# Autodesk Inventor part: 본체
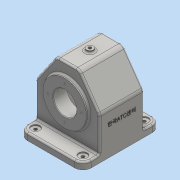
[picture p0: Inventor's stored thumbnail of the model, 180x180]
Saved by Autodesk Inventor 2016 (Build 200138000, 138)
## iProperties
Created: 2022-12
Part Number: 본체
Material: 일반
Document SubType Name: Modeling
Designer: PC-1-2
Density: 1 g/cm^3
Appearance: 기본값
Author: PC-1-2
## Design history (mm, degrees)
sketch "스케치1"
  geometry: L1 (-55, -67)-(55, -67); L2 (55, -67)-(55, 67); L3 (55, 67)-(-55, 67); L4 (-55, 67)-(-55, -67); L5 (-55, -67)-(55, 67); L6 (55, -67)-(-55, 67); 1 further point
  constraints: 12 end point, 2 midpoint, 2 parallel, 1 horizontal, 1 perpendicular
  dimensions: "d0" = 134 distance between parallel lines of L1 L3; "d1" = 110 distance between parallel lines of L2 L4
extrude "돌출1" new body sketch "스케치1" distance "d2" = 12; taper "d3" = 0 deg
sketch "스케치2"
  geometry: L1 (55, 12)-(-55, 12) reference; L2 (55, 12)-(55, 72); L3 (55, 72)-(19.99, 122); L4 (19.99, 122)-(-19.99, 122); L5 (-19.99, 122)-(-55, 72); L6 (-55, 72)-(-55, 12); L7 (55, 0)-(-55, 0) reference; 1 further point
  constraints: 10 end point, 1 horizontal alignment, 1 parallel, 1 perpendicular, 1 vertical
  dimensions: "d4" = 122 distance between parallel lines of L7 L4; "d5" = 72 distance from line of L7 L2.end; "d6" = 35 deg angle of L3 L2; "d7" = 35 deg angle of L6 L5
extrude "돌출2" join sketch "스케치2" stored distance "d8" = 77; taper "d9" = 0 deg
sketch "스케치3"
  geometry: C1 r 6 at (19.99, -38.5); 1 further point
  constraints: 1 centre point, 1 coincident
  dimensions: "d10" = 12 diameter of C1
extrude "돌출3" join sketch "스케치3" distance "d11" = 4; taper "d12" = 0 deg
sketch "스케치4"
  geometry: L1 (-55, 0)-(55, 0) reference; C1 r 37.5 at (0, 65); 2 further points
  constraints: 1 centre point, 1 midpoint, 1 vertical alignment
  dimensions: "d13" = 75 diameter of C1; "d14" = 65 distance from line of L1 C1.centre
extrude "돌출4" join sketch "스케치4" distance "d15" = 5; taper "d16" = 0 deg
sketch "스케치5"
  geometry: L1 (55, 0)-(-55, 0) reference; C1 r 31 at (0, -65); 2 further points
  constraints: 1 centre point, 1 midpoint, 1 vertical alignment
  dimensions: "d17" = 65 distance from line of L1 C1.centre; "d18" = 62 diameter of C1
extrude "돌출5" join sketch "스케치5" distance "d19" = 10; taper "d20" = 0 deg
sketch "스케치6"
  geometry: L1 (55, 72)-(19.99, 122) reference; L2 (19.99, 122)-(-19.99, 122) reference; L3 (-19.99, 122)-(-55, 72) reference; L4 (-55, 72)-(-55, 12) reference; L5 (55, 12)-(55, 72) reference; L6 (55, 0)-(55, 12) reference; L7 (-55, 0)-(-55, 12) reference; L8 (-50, 0)-(-50, 12); L9 (-50, 12)-(-50, 70.424); L10 (-50, 70.424)-(-17.387, 117); L11 (-17.387, 117)-(17.387, 117); L12 (17.387, 117)-(50, 70.424); L13 (50, 70.424)-(50, 12); L14 (50, 12)-(50, 0); L15 (50, 0)-(-50, 0); 2 further points
  constraints: 16 end point, 1 horizontal alignment, 1 midpoint, 1 perpendicular, 6 other
  dimensions: "d21" = 5 distance between parallel lines of L1 L12
extrude "돌출6" cut sketch "스케치6" stored distance "d22" = 67; taper "d23" = 0 deg
sketch "스케치7"
  geometry: C1 r 27 at (0, -65); C2 r 37.5 at (0, -65) reference; 1 further point
  constraints: 1 centre point, 1 concentric
  dimensions: "d24" = 54 diameter of C1
extrude "돌출7" join sketch "스케치7" distance "d25" = 14; taper "d26" = 0 deg
feature "면 기울기1" dims angle "d27" = 45 deg
hole "구멍1" diameter "d30" = 40; stored, may be unused: countersink angle "d34" = 90 deg, drill point angle "d36" = 0 deg; dims "d28" = 10, "d29" = 10, "d31" = 6, "d32" = 4, "d33" = 2, "d35" = 100
sketch "스케치8" dims "d37" = 58
  geometry: C1 r 37.5 at (0, 0) reference; 3 further points
  constraints: 2 vertical alignment, 3 other
hole "구멍2" sketch "스케치8" at (0, 29) diameter "d38" = 2.459; stored, may be unused: countersink angle "d42" = 90 deg, drill point angle "d44" = 118 deg; dims "d39" = 6, "d40" = 4, "d41" = 2, "d43" = 8
sketch "스케치9" dims "d48" = 52
  geometry: C1 r 31 at (0, 0) reference; 3 further points
  constraints: 2 vertical alignment, 3 other
hole "구멍3" sketch "스케치9" at (0, -26) diameter "d49" = 2.459; stored, may be unused: countersink angle "d53" = 90 deg, drill point angle "d55" = 118 deg; dims "d50" = 6, "d51" = 4, "d52" = 2, "d54" = 8
hole "구멍4" diameter "d61" = 5.188; stored, may be unused: countersink angle "d65" = 90 deg, drill point angle "d67" = 0 deg; dims "d59" = 10, "d60" = 10, "d62" = 61, "d63" = 4, "d64" = 2, "d66" = 61
fillet "모깎기1" dims "d68" = 14
hole "구멍5" diameter "d71" = 5.5; stored, may be unused: countersink angle "d75" = 90 deg, drill point angle "d77" = 0 deg; dims "d69" = 10, "d70" = 10, "d72" = 61, "d73" = 15, "d74" = 2, "d76" = 12
fillet "모깎기2" dims "d84" = 10
fillet "모깎기3" dims "d85" = 3
fillet "모깎기4" dims "d86" = 3
fillet "모깎기5" dims "d87" = 3
fillet "모깎기6" dims "d88" = 3
fillet "모깎기7" dims "d89" = 5
fillet "모깎기8" dims "d90" = 3
fillet "모깎기9" dims "d91" = 3
chamfer "모따기1" distance "d92" = 1; stored, may be unused: second distance "d93" = 2, angle "d94" = 45 deg
sketch "스케치10"
  geometry: L1 (-54, 28)-(-54, 78); L2 (-54, 78)-(-46, 78); L3 (-46, 78)-(-46, 28); L4 (-46, 28)-(-54, 28); L5 (-50, 28)-(-50, 78); L6 (-54, 53)-(-46, 53); L7 (0, 0)-(0, 106) reference; L8 (-68.847, 14.5)-(-15, 14.5) reference; 1 further point
  constraints: 4 end point, 4 midpoint, 2 other
  dimensions: "d95" = 8 distance between parallel lines of L3 L1; "d96" = 50 distance between parallel lines of L4 L2; "d97" = 50 distance between parallel lines of L7 L5; "d98" = 38.5 distance between parallel lines of L8 L6
feature "엠보싱1" sketch "스케치10" dims "d0" = 134, "d1" = 110, "d99" = 0.5, "d100" = 0
node "솔리드1"
pattern_circular "원형 패턴1" dims angle "d46" = 360 deg
pattern_circular "원형 패턴2" dims angle "d57" = 360 deg
pattern_linear "직사각형 패턴1" dims "d80" = 82, "d83" = 106
